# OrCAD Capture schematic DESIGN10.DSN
size A
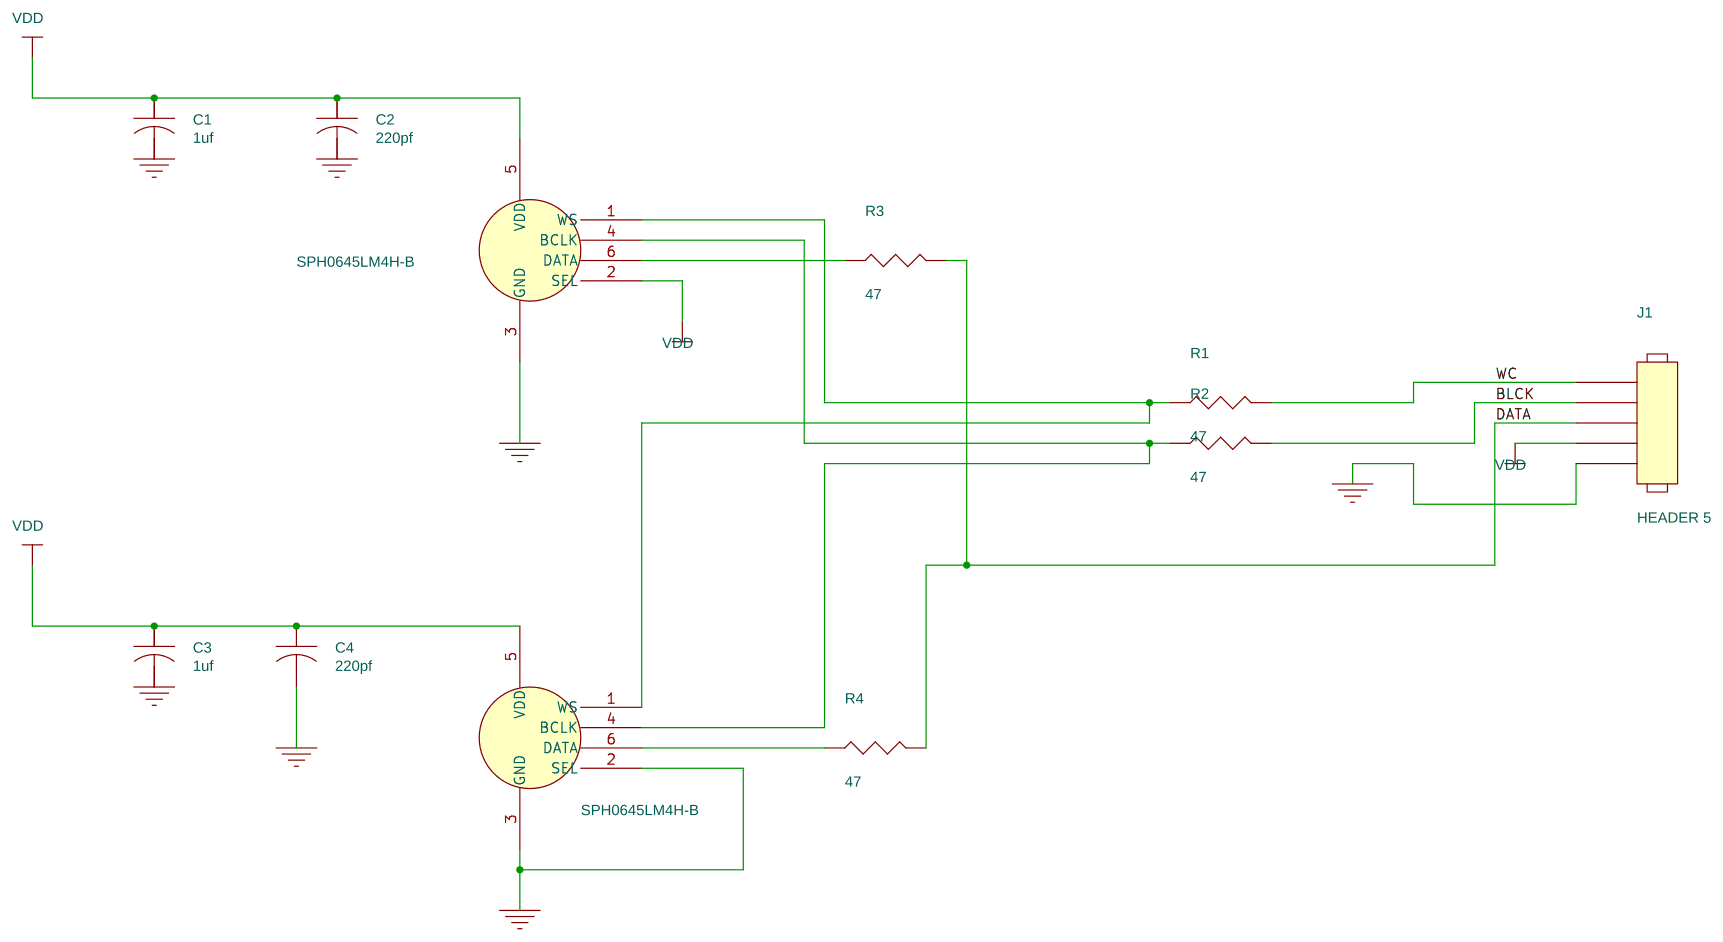
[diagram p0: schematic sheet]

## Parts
C1  1uf  [GU-CAPCYL100]
C2  220pf  [GU-CAPCYL100]
C3  1uf  [GU-CAPCYL100]
C4  220pf  [GU-CAPCYL100]
J1  HEADER 5  [GU-MOLEX5]
R1  47  [GU-RC300]
R2  47  [GU-RC300]
R3  47  [GU-RC300]
R4  47  [GU-RC300]
U1  SPH0645LM4H-B  [mic_sph0645lm4h-b]
U2  SPH0645LM4H-B  [mic_sph0645lm4h-b]

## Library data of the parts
C1-C4 = CAPACITOR
J1 = HEADER_5
R1-R4 = RESISTOR
U1 U2 = SPH0645LM4H-B

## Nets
GND_POWER: C1.2 C2.2 C3.2 C4.2 J1.1 U1.3(GND) U2.2(SEL) U2.3(GND)
VDD: C1.1 C2.1 C3.1 C4.1 J1.2 U1.2(SEL) U1.5(VDD) U2.5(VDD)
BLCK: J1.4 R2.2
DATA: J1.3 R3.2 R4.2
WC: J1.5 R1.2
N01929: R3.1 U1.6(DATA)
N01947: R4.1 U2.6(DATA)
N02065: R1.1 U1.1(WS) U2.1(WS)
N02132: R2.1 U1.4(BCLK) U2.4(BCLK)
